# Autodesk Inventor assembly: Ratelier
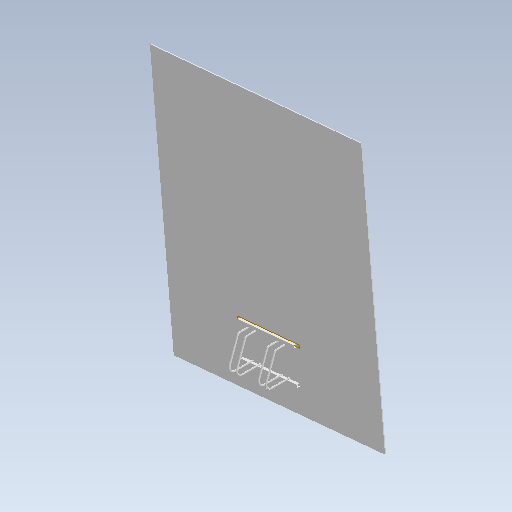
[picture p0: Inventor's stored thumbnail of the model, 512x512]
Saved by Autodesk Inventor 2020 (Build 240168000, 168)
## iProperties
Created: 2021-01
Part Number: Ratelier
Document SubType Name: Assembly
Designer: bruno
Author: bruno
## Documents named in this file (4)
- C:\Users\bruno\Documents\1-Cours-2020-21\1STI2D-2020-21\IT\6. Antivol\Inventor-Antivol\Ratelier.iam
- C:\Users\bruno\Documents\1-Cours-2020-21\1STI2D-2020-21\IT\6. Antivol\Inventor-Antivol\longeron.ipt
- C:\Users\bruno\Documents\1-Cours-2020-21\1STI2D-2020-21\IT\6. Antivol\Inventor-Antivol\Arceau.ipt
- C:\Users\bruno\Documents\1-Cours-2020-21\1STI2D-2020-21\IT\6. Antivol\Inventor-Antivol\Sol.ipt
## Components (7 placed, 3 different names)
1. longeron:1 — Affleurement:1, Affleurement:2, Tangente:5, Tangente:6, Tangente:7, Tangente:8, Placage:1, Tangente:11, Affleurement:7, Affleurement:8
2. longeron:2 — Affleurement:1, Affleurement:2, Tangente:2, Tangente:3, Tangente:4, Affleurement:3, Affleurement:4, Affleurement:5, Affleurement:6, Placage:1, Tangente:9
3. Arceau:1 — Tangente:2, Affleurement:5, Tangente:7, Tangente:10
4. Arceau:2 — Affleurement:4, Tangente:8, Tangente:9, Tangente:10
5. Arceau:3 — Tangente:4, Tangente:5, Affleurement:3, Tangente:12
6. Arceau:4 — Tangente:3, Affleurement:6, Tangente:6, Tangente:11, Tangente:12
7. Sol:1 — Affleurement:7, Affleurement:8
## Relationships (20: Tangent 11, Flush 8, Mate 1)
- Affleurement:1 [Flush]: longeron:1 ↔ longeron:2
- Affleurement:2 [Flush]: longeron:1 ↔ longeron:2
- Tangente:2: longeron:2 ↔ Arceau:1
- Tangente:3: longeron:2 ↔ Arceau:4
- Tangente:4: longeron:2 ↔ Arceau:3
- Tangente:5: longeron:1 ↔ Arceau:3
- Affleurement:3 [Flush]: longeron:2 ↔ Arceau:3
- Affleurement:4 [Flush]: longeron:2 ↔ Arceau:2
- Affleurement:5 [Flush]: longeron:2 ↔ Arceau:1
- Affleurement:6 [Flush]: longeron:2 ↔ Arceau:4
- Tangente:6: longeron:1 ↔ Arceau:4
- Tangente:7: longeron:1 ↔ Arceau:1
- Tangente:8: longeron:1 ↔ Arceau:2
- Placage:1 [Mate]: longeron:1 ↔ longeron:2
- Tangente:9: longeron:2 ↔ Arceau:2
- Tangente:10: Arceau:1 ↔ Arceau:2
- Tangente:11: longeron:1 ↔ Arceau:4
- Tangente:12: Arceau:3 ↔ Arceau:4
- Affleurement:7 [Flush]: longeron:1 ↔ Sol:1
- Affleurement:8 [Flush]: longeron:1 ↔ Sol:1
